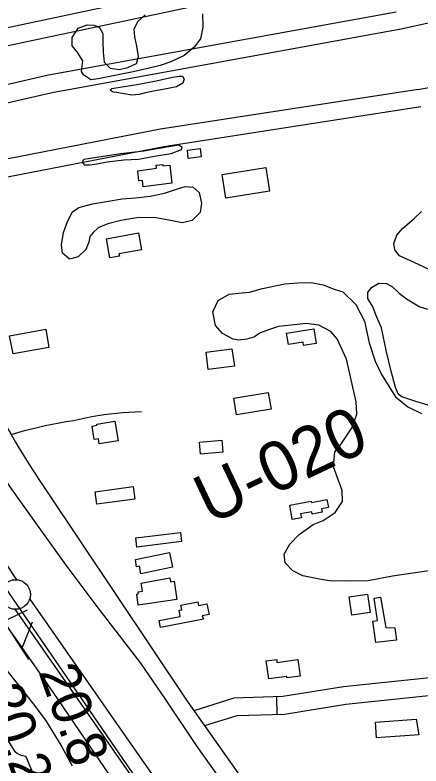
# Model space of a CAD drawing. Extents: x 3540316 to 3578335, y 553172 to 578787.
# Drawn here: x 3553188 to 3553873, y 562816 to 564084 of the extents above; entities that cross this region are included whole.
import ezdxf

# ---------------------------------------------------------------- set-up
doc = ezdxf.new("R2010")
doc.units = 0
for name, color, linetype in [('V-BLDG-OTLN', 7, 'Continuous'), ('V-FLOD-BASE', 7, 'Continuous'), ('V-LEVE-TOET', 7, 'Continuous'), ('V-RIVR-RANG', 7, 'Continuous'), ('V-RIVR-RANG-IDEN', 7, 'Continuous'), ('V-ROAD-CNTR', 7, 'Continuous'), ('V-RRAP-FSHR', 7, 'Continuous'), ('V-SITE-VEGE', 7, 'Continuous'), ('V-SURV-LINE', 7, 'Continuous'), ('V-TOPO-MINR', 7, 'Continuous'), ('V-TOPO-SHOR', 7, 'Continuous')]:
    doc.layers.add(name, color=color, linetype=linetype)

msp = doc.modelspace()

# ---------------------------------------------------------------- linework, layer by layer
at = {"layer": 'V-BLDG-OTLN'}
for points in [[(3553478.8, 563855.7), (3553500, 563858.6), (3553501.9, 563844.4), (3553480, 563841.4)], [(3553452.2, 563800), (3553404, 563793.8), (3553402.6, 563804.5), (3553396.8, 563803.7), (3553394.6, 563821), (3553426.4, 563825.1), (3553425.7, 563830.3), (3553436.9, 563831.8), (3553437.2, 563829.1), (3553448.8, 563830.6)], [(3553537.2, 563814.4), (3553610.7, 563826.5), (3553617.2, 563786.8), (3553543.5, 563774.7)], [(3553341.8, 563705.9), (3553395.9, 563716.1), (3553401.2, 563687.7), (3553363, 563680.5), (3553363.7, 563677), (3553347.5, 563673.9)], [(3553178.3, 563542.4), (3553239.4, 563553.4), (3553244.9, 563522.9), (3553184.4, 563512)], [(3553645.9, 563546.7), (3553691.7, 563554.1), (3553695.6, 563529.4), (3553674.7, 563526), (3553673.8, 563531.8), (3553649.2, 563527.8)], [(3553558.1, 563491.2), (3553513.8, 563485.4), (3553510, 563514.8), (3553553.8, 563520.5)], [(3553620, 563418.5), (3553561.6, 563409), (3553557, 563437.2), (3553614.7, 563446.7)], [(3553356.1, 563398.2), (3553361.5, 563365.3), (3553329.8, 563360.2), (3553328.5, 563368.4), (3553321.2, 563367.3), (3553317.5, 563390.1), (3553325.8, 563391.4), (3553325.5, 563393.2)], [(3553498.7, 563362.7), (3553536.4, 563366.5), (3553538.4, 563346.2), (3553500.8, 563342.4)], [(3553390, 563266.7), (3553325.7, 563258), (3553322.9, 563279.2), (3553386.8, 563287.9)], [(3553651.3, 563256.4), (3553687.6, 563263.2), (3553688, 563261), (3553714.1, 563265.9), (3553716.6, 563252.8), (3553705, 563250.6), (3553706.2, 563244.5), (3553689.4, 563241.3), (3553688.6, 563245.6), (3553669.7, 563242), (3553671, 563235.1), (3553655.3, 563232.2)], [(3553391.6, 563201.2), (3553466.9, 563210.7), (3553468.8, 563195.1), (3553393, 563185.5)], [(3553390.7, 563164.7), (3553448.3, 563176.9), (3553453.5, 563152.1), (3553400.1, 563140.9), (3553397.4, 563153.6), (3553392.7, 563152.6)], [(3553460.6, 563097.4), (3553395.5, 563087.9), (3553392.9, 563106.3), (3553395.7, 563106.7), (3553395.2, 563110.2), (3553402.7, 563111.3), (3553400.7, 563124.9), (3553448.6, 563133.7), (3553449.8, 563127), (3553456.2, 563128.1)], [(3553751.6, 563102), (3553782.4, 563106.4), (3553786.8, 563075.5), (3553756.2, 563071.2)], [(3553804.6, 563101.5), (3553813.7, 563050.2), (3553828.7, 563049.7), (3553831.4, 563028.7), (3553796.7, 563024.7), (3553791.4, 563060.6), (3553799.3, 563061.8), (3553793.7, 563099.8)], [(3553505.5, 563064.3), (3553433.1, 563050.1), (3553430.8, 563061.7), (3553466.5, 563068.7), (3553464.4, 563079.2), (3553469.2, 563080.2), (3553467.7, 563088), (3553496, 563093.5), (3553497.2, 563087.3), (3553511.5, 563090.1), (3553515, 563072), (3553503.6, 563069.8)], [(3553629.4, 562991), (3553664.9, 562995.9), (3553668.8, 562968), (3553646.6, 562964.9), (3553646.2, 562967.4), (3553615.8, 562963.2), (3553611.6, 562993.9), (3553629.2, 562996.3)], [(3553868.9, 562868.7), (3553797.8, 562863.7), (3553795.9, 562890.5), (3553864.5, 562895.3)]]:
    msp.add_lwpolyline(points, close=True, dxfattribs=at)
at = {"layer": 'V-FLOD-BASE'}
msp.add_lwpolyline([(3553541, 562582), (3553465.4, 562690.9), (3553371.1, 562826.3), (3553293.1, 562940.2), (3553212.3, 563057.7), (3553142.2, 563159.5), (3553076.4, 563261.4), (3553007, 563366), (3552987.6, 563401.2), (3552961.7, 563449.6), (3552955.7, 563467.6), (3552939.1, 563545.1), (3552931.6, 563609.4), (3552921.3, 563737.5), (3552912.3, 563855.1), (3552902.7, 563988.4), (3552895.1, 564071)], dxfattribs=at)
at = {"layer": 'V-LEVE-TOET'}
for points in [[(3552985, 564262), (3552987.6, 564234.7), (3552984, 564184.2), (3552986.3, 564129.7), (3552990.4, 564054.5), (3553001.7, 563955.5), (3553005.8, 563867), (3553016.5, 563791), (3553025.8, 563691.6), (3553036.8, 563628.2), (3553047.6, 563548), (3553059.3, 563502.6), (3553084, 563437.3), (3553103.4, 563403), (3553134, 563352.3), (3553182.6, 563281.7), (3553219.4, 563230.6), (3553273.6, 563155.4), (3553327.4, 563083.3), (3553399.4, 562989.8), (3553440.9, 562929.3), (3553493.2, 562850.9), (3553543, 562781.2)], [(3552839, 564065.5), (3552844.1, 564057.4), (3552852.1, 564038.3), (3552856.9, 564016.8), (3552862.9, 563945.4), (3552870.6, 563848.5), (3552879.5, 563742.3), (3552889.6, 563646.7), (3552905.4, 563560.4), (3552919.2, 563480.8), (3552933.7, 563428.6), (3552955.5, 563382.2), (3552993, 563322.3), (3553041.5, 563252.3), (3553090.9, 563175.7), (3553141.1, 563095.9), (3553188.4, 563031.4), (3553251.2, 562940.8), (3553305.6, 562861.9), (3553361.3, 562780.2), (3553424.1, 562683.7), (3553471.1, 562617.6), (3553529.1, 562534.8)]]:
    msp.add_lwpolyline(points, dxfattribs=at)
at = {"layer": 'V-RIVR-RANG'}
msp.add_line((3553207.9, 563079.1), (3552503.5, 562744.2), dxfattribs=at)
at = {"layer": 'V-ROAD-CNTR'}
msp.add_line((3553630.1, 562903.2), (3553629.2, 562933.1), dxfattribs=at)
for points in [[(3553025.8, 564031.2), (3553685.2, 564171.6)], [(3553026.5, 564000.7), (3553691.5, 564142.3)], [(3553836.8, 564059.9), (3554133.5, 564126)], [(3553029.2, 563933.1), (3553243.9, 563982.6), (3553830.9, 564089.3)], [(3553867.6, 563958.2), (3554540.8, 564080.3)], [(3553031.2, 563902.8), (3553250, 563953.2), (3553836.2, 564059.8)], [(3553868, 563958.3), (3553433.3, 563891), (3553039.9, 563814.4)], [(3553872.6, 563928.6), (3553438.5, 563861.5), (3553043.8, 563784.6)], [(3553180.8, 563375.7), (3553192.2, 563379.2), (3553203.8, 563382.4), (3553215.4, 563385.5), (3553227, 563388.3), (3553238.7, 563391), (3553250.5, 563393.4), (3553262.3, 563395.6), (3553274.1, 563397.7), (3553286, 563399.5), (3553296.2, 563401.9), (3553306.6, 563404.1), (3553317, 563406.1), (3553327.4, 563407.9), (3553337.8, 563409.5), (3553348.3, 563410.9), (3553358.8, 563412), (3553369.4, 563413), (3553379.9, 563413.7), (3553390.5, 563414.2), (3553401, 563414.5)], [(3553239.6, 563282.3), (3553477.1, 562927.2), (3553915.4, 562306.8)], [(3553925.7, 562969.3), (3553742, 562950.1), (3553639.8, 562933.5), (3553557.1, 562931), (3553489.5, 562909.6)], [(3553928.9, 562939.5), (3553746, 562920.3), (3553642.6, 562903.5), (3553562.2, 562901.1), (3553507.6, 562883.9)]]:
    msp.add_lwpolyline(points, dxfattribs=at)
msp.add_arc((3554411.2, 564082.2), 1418.6, 200.6563, 214.3235, dxfattribs=at)
at = {"layer": 'V-RRAP-FSHR'}
msp.add_line((3553198.8, 563014.3), (3553217.3, 563059.5), dxfattribs=at)
msp.add_lwpolyline([(3552848.7, 564047.4), (3552868.9, 563881.3), (3552877.4, 563741.8), (3552886.7, 563571.4), (3552928.6, 563439.5), (3552979.5, 563356), (3553061.4, 563227.5), (3553195.9, 563018.8), (3553210.1, 562996.3)], dxfattribs=at)
at = {"layer": 'V-SITE-VEGE'}
for points in [[(3553503.9, 564086.1), (3553504.8, 564063.4), (3553500.6, 564043.7), (3553490.1, 564029.5), (3553473, 564015.7), (3553450.7, 564005), (3553432.7, 563998.6), (3553411.6, 563993.7), (3553386.9, 563987.7), (3553364.6, 563983.2), (3553347.7, 563979.9), (3553327.8, 563975.9), (3553315.6, 563974.6), (3553310.5, 563977.7), (3553303.4, 563983.1), (3553299.8, 563988.6), (3553302.1, 564006.3), (3553292.2, 564021.5), (3553284.2, 564031.6), (3553283.8, 564045.8), (3553294.2, 564061.9), (3553309.1, 564067.1), (3553320.9, 564066.8), (3553330.3, 564062.5), (3553335.9, 564052.8), (3553336, 564038.3), (3553336.1, 564021.4), (3553338.2, 564004.2), (3553348.4, 563994.4), (3553363.7, 563991.8), (3553377.8, 563995), (3553392.7, 564002.2), (3553396.1, 564014), (3553392.9, 564031.2), (3553389.6, 564046.9), (3553388.7, 564060.6), (3553395.3, 564073.6), (3553407, 564083.9)], [(3553886.2, 563145.5), (3553824.5, 563136.5), (3553783.4, 563128.6), (3553751.7, 563128.1), (3553718.6, 563129.1), (3553701.6, 563131.8), (3553673.5, 563137.3), (3553656.5, 563145.9), (3553643.8, 563159), (3553642.1, 563173.7), (3553651.4, 563190.7), (3553667.4, 563207.2), (3553690.7, 563223.7), (3553707.5, 563230.6), (3553727.9, 563244.1), (3553740.2, 563262.7), (3553739.9, 563281.1), (3553725.3, 563321.4), (3553727.2, 563346.5), (3553737.3, 563359.1), (3553756.8, 563387.4), (3553764.6, 563410.3), (3553763.5, 563430.9), (3553747, 563502.9), (3553731.1, 563537.2), (3553720.6, 563549.6), (3553700.5, 563560.4), (3553679.1, 563563), (3553653.4, 563560.4), (3553632.1, 563557.9), (3553615.2, 563552.5), (3553602, 563547.2), (3553590.4, 563540.4), (3553578.6, 563536.5), (3553565.4, 563534.8), (3553555.8, 563536.9), (3553538, 563546.2), (3553526, 563560), (3553521.3, 563582.8), (3553530.6, 563602.1), (3553548.8, 563612.7), (3553570.9, 563615.2), (3553583.4, 563616.1), (3553605.4, 563622.3), (3553642.8, 563630.2), (3553664.9, 563632), (3553687.7, 563632.3), (3553707.6, 563628.2), (3553726.2, 563621.1), (3553740.9, 563616.9), (3553762.6, 563595.1), (3553777.7, 563567.4), (3553785.6, 563530.7), (3553795.7, 563499.9), (3553806.3, 563477.2), (3553829.7, 563439.3), (3553850.5, 563422.6), (3553873.5, 563411.2)], [(3552849.1, 563573.6), (3552857.9, 563540.6), (3552863.5, 563512.8), (3552874, 563473.9), (3552881.2, 563441.5), (3552888.9, 563406), (3552903.2, 563373.2), (3552918.6, 563346.4), (3552942.3, 563305.1), (3552959.7, 563273.6), (3552979.5, 563242.9), (3553025.3, 563176), (3553046.6, 563146.5), (3553068.7, 563118.5), (3553094.3, 563087), (3553122.2, 563052), (3553153, 563010.8), (3553170, 562982.8), (3553197.6, 562947.5), (3553216.5, 562923.4), (3553239, 562893.8), (3553266.3, 562848.7), (3553284.1, 562816.4)]]:
    msp.add_lwpolyline(points, dxfattribs=at)
for points in [[(3553351, 563959.6), (3553396.5, 563966.9), (3553425.8, 563973), (3553453.2, 563978.7), (3553464.6, 563980.7), (3553470.5, 563980.8), (3553473.3, 563975.7), (3553471, 563968.6), (3553460.4, 563962.7), (3553443.2, 563959.4), (3553427.5, 563956.6), (3553409.9, 563952.9), (3553397, 563949.7), (3553384.8, 563948.4), (3553358.9, 563952.9), (3553353, 563953.7), (3553348.3, 563956.8)], [(3553303.6, 563840.8), (3553365.5, 563849.9), (3553405.1, 563854.8), (3553447, 563861.8), (3553464.2, 563864.7), (3553469.3, 563861.6), (3553468.2, 563856.5), (3553450.6, 563849.3), (3553422.8, 563844.8), (3553395.8, 563839.9), (3553371.5, 563838.9), (3553342.9, 563835.6), (3553325.6, 563831.9), (3553313.9, 563830.3), (3553305.3, 563830.6), (3553301.7, 563835.7), (3553302.5, 563838)], [(3553312, 563700.5), (3553307, 563688.3), (3553294.2, 563675.6), (3553279.3, 563672), (3553267.9, 563681.7), (3553266.2, 563696.2), (3553269.2, 563717), (3553276.1, 563735.1), (3553284.6, 563751.7), (3553295.2, 563759.2), (3553318.6, 563765.2), (3553341.8, 563768.9), (3553368.4, 563773.4), (3553390.7, 563775.5), (3553415.8, 563778.1), (3553440.1, 563783.3), (3553460.4, 563789.7), (3553474.5, 563794.5), (3553488.2, 563793.5), (3553498.5, 563784.1), (3553502.6, 563766.5), (3553499.9, 563750.8), (3553486.3, 563737), (3553469.8, 563732.9), (3553447.1, 563737.5), (3553422.3, 563742), (3553392.9, 563741.8), (3553366.3, 563736.9), (3553344.4, 563731.3), (3553327.9, 563724.5), (3553319.4, 563717), (3553313.9, 563709.9)]]:
    msp.add_lwpolyline(points, close=True, dxfattribs=at)
at = {"layer": 'V-SURV-LINE'}
for points in [[(3553040.8, 563355.8), (3553190, 563130.8)], [(3553212.3, 563098), (3553952.7, 562036.7)], [(3553928.1, 562019.5), (3553187.7, 563080.9)]]:
    msp.add_lwpolyline(points, dxfattribs=at)
msp.add_circle((3553188.6, 563105.8), 25, dxfattribs=at)
at = {"layer": 'V-TOPO-MINR'}
msp.add_lwpolyline([(3553897.2, 561177.7), (3553206.6, 562832.1), (3553206.2, 562832.2), (3553205.8, 562832.2), (3553205.7, 562832.2), (3553205.5, 562832.2), (3553198.1, 562834.2), (3553194.5, 562835.5), (3553191.3, 562837.4), (3553188.6, 562839.9), (3553186.3, 562842.9), (3552944.6, 563237.6), (3552899.4, 563310.8), (3552853.7, 563383.6), (3552807.3, 563456), (3552760.4, 563528), (3552713.9, 563600.4), (3552668.4, 563673.3), (3552624.4, 563747.1), (3552581.4, 563821.5), (3552523.8, 563923.4), (3552487.4, 563987.3), (3552450.7, 564051), (3552413.6, 564114.4)], dxfattribs=at)
at = {"layer": 'V-TOPO-SHOR'}
for points in [[(3553887.8, 563653.6), (3553861.4, 563666.4), (3553836.4, 563677.2), (3553828.4, 563687.3), (3553826.8, 563698), (3553832, 563712.2), (3553841.6, 563723.5), (3553852.6, 563733), (3553861.7, 563740.9), (3553873.8, 563752.2)], [(3553894.6, 563422.5), (3553864.3, 563431.3), (3553840.3, 563439.7), (3553834.9, 563443.1), (3553829.9, 563455.2), (3553822.2, 563482.8), (3553814.4, 563515.3), (3553806, 563556.1), (3553798, 563574), (3553790.9, 563592.3), (3553782.9, 563605.4), (3553782.8, 563615.6), (3553789, 563624), (3553801.5, 563631), (3553814.7, 563630.7), (3553824.5, 563625), (3553835.8, 563614.4), (3553848.1, 563604.9), (3553870.7, 563591.1), (3553883.9, 563587.4)]]:
    msp.add_lwpolyline(points, dxfattribs=at)

# ---------------------------------------------------------------- texts
at = {"layer": 'V-RIVR-RANG'}
for s, p in [('20.8', (3553226.7, 562975.3)), ('20.2', (3553132.6, 562941.6))]:
    msp.add_text(s, height=67, rotation=289.5883, dxfattribs=at).set_placement(p)
at = {"layer": 'V-RIVR-RANG-IDEN'}
msp.add_text('U-020', height=83, rotation=25.2903, dxfattribs=at).set_placement((3553516.3, 563222.8))

doc.saveas('drawing.dxf')
